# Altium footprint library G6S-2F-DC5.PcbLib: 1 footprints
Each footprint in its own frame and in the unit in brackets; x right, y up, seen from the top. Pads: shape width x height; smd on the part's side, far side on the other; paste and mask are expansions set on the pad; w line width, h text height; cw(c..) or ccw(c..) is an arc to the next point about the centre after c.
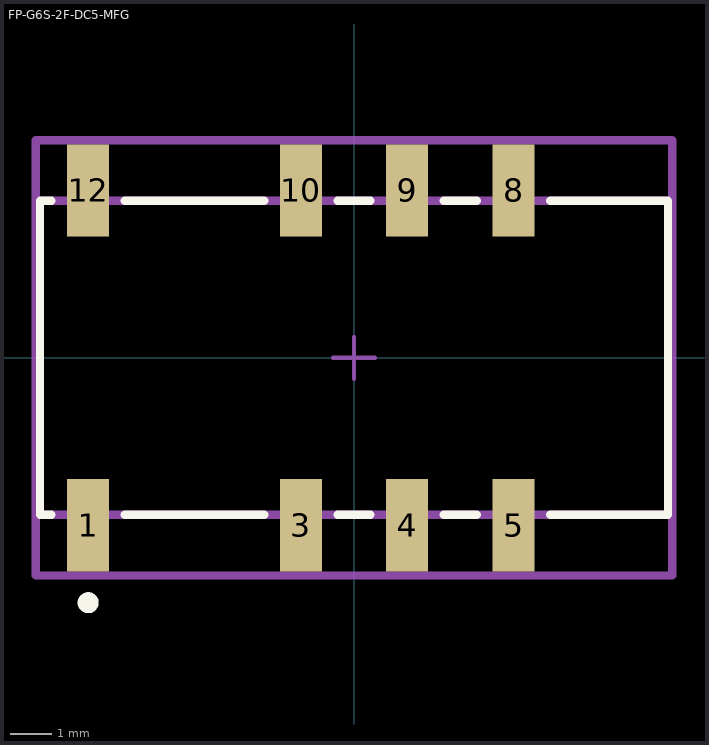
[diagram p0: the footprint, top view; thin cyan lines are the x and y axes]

## FP-G6S-2F-DC5-MFG [mm]
pads (8):
  rect 1x2.2 smd paste+0 mask+0: 1(-6.35,-4) 3(-1.27,-4) 4(1.27,-4) 5(3.81,-4) 8(3.81,4) 9(1.27,4) 10(-1.27,4) 12(-6.35,4)
Top Overlay:
  circle w0.25: c-6.35,-5.85 r0.125
  lines w0.2: -7.225,-3.75 -7.5,-3.75 -7.5,3.75 -7.225,3.75 ; -5.475,-3.75 -2.145,-3.75 ; -5.475,3.75 -2.145,3.75 ; -0.395,-3.75 0.395,-3.75 ; -0.395,3.75 0.395,3.75 ; 2.145,-3.75 2.935,-3.75 ; 2.145,3.75 2.935,3.75 ; 4.685,-3.75 7.5,-3.75 7.5,3.75 4.685,3.75
Top Assembly:
  lines w0.2: -7.6,-5.2 -7.6,5.2 7.6,5.2 7.6,-5.2 -7.6,-5.2
  text ".Designator" at 0,-0.001 h1
Top 3D Body:
  lines w0.2: -7.5,-3.75 -7.5,3.75 7.5,3.75 7.5,-3.75 -7.5,-3.75
Top Courtyard:
  lines w0.2: -7.6,-5.2 -7.6,5.2 7.6,5.2 7.6,-5.2 -7.6,-5.2
Top Component Center:
  lines w0.1: -0.5,0 0.5,0 ; 0,-0.5 0,0.5
3D body "Relay_Omron_G6S-2F-DC5_eec.STEP": height 0.25, standoff 0, extent -7.6,-5.2 7.6,5.2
